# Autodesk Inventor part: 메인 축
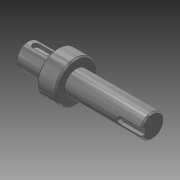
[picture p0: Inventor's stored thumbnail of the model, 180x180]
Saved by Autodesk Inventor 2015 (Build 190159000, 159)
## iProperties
Created: 2014-10
Part Number: 메인 축
Document SubType Name: Modeling
Designer: KYOUNG IL JANG
Density: 7.86 g/cm^3
Mass: 230.24 g
Surface Area: 74.3518 cm^2
Volume: 29.2926 cm^3
Material: 강철, 연강
Appearance: 반광택
Author: SeoGD™ [www.esajin.kr]
Revision Number: 1
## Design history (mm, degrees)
sketch "스케치1"
  geometry: L1 (10.497, -57.5)-(102.497, -57.5); L2 (10.497, -66)-(32.497, -66); L3 (32.497, -72.5)-(46.5, -72.5); L4 (46.5, -66)-(102.497, -66); L5 (102.497, -66)-(102.497, -57.5); L6 (10.497, -66)-(10.497, -57.5); L7 (46.5, -69.749)-(46.5, -45.251) reference; L8 (46.5, -72.5)-(46.5, -66); L9 (32.497, -72.5)-(32.497, -66); L10 (32.497, -35)-(32.497, -80) reference; 2 further points
  constraints: 16 end point, 2 parallel, 2 perpendicular, 2 point on line, 1 collinear, 1 horizontal, 1 midpoint
  dimensions: "d0" = 17 diameter of L4 L1; "d1" = 30 diameter of L3 L1; "d2" = 22 distance of L2.start L2.end; "d3" = 55.99692 distance of L4.start L4.end (derived); "d5" = 17 diameter of L2 L1; "d19" = 70 distance between parallel lines of L5 L9
revolve "회전1" sketch "스케치1" stored, may be unused: angle "d4" = 90 deg
chamfer "모따기1" distance "d6" = 1; stored, may be unused: second distance "d7" = 2, angle "d8" = 45 deg
node "작업 평면1"
sketch "스케치2"
  geometry: L1 (-11, -7.5)-(-11, 7.5) reference; L2 (-4.5, 2.5)-(4.5, 2.5); L3 (4.5, -2.5)-(-4.5, -2.5); A1 r 2.5 centre (4.5, 0) between (4.5, -2.5) and (4.5, 2.5); A2 r 2.5 centre (-4.5, 0) between (-4.5, 2.5) and (-4.5, -2.5); 2 further points
  constraints: 4 end point, 4 point on circle, 4 tangent, 2 centre point, 1 horizontal alignment, 1 midpoint, 1 parallel, 1 perpendicular
  dimensions: "d9" = 5 distance between parallel lines of L3 L2; "d10" = 14 dimension on A1 A2; "d11" = 4 distance edge to line of A2 L1
extrude "돌출1" cut sketch "스케치2" distance "d12" = 3; taper "d13" = 0 deg
node "작업 평면2"
sketch "스케치3"
  geometry: L1 (27.998, 7.5)-(27.998, -7.5) reference; L2 (27.998, 2.5)-(12.498, 2.5); L3 (12.498, -2.5)-(27.998, -2.5); A1 r 2.5 centre (12.498, 0) between (12.498, 2.5) and (12.498, -2.5); 2 further points
  constraints: 4 end point, 2 perpendicular, 2 point on circle, 2 point on line, 2 tangent, 1 centre point, 1 horizontal alignment, 1 midpoint
  dimensions: "d14" = 5 distance between parallel lines of L3 L2; "d15" = 18 dimension on A1 L1
extrude "돌출2" cut sketch "스케치3" distance "d16" = 3; taper "d17" = 0 deg
node "솔리드1"
node "참조4"
node "참조5"
